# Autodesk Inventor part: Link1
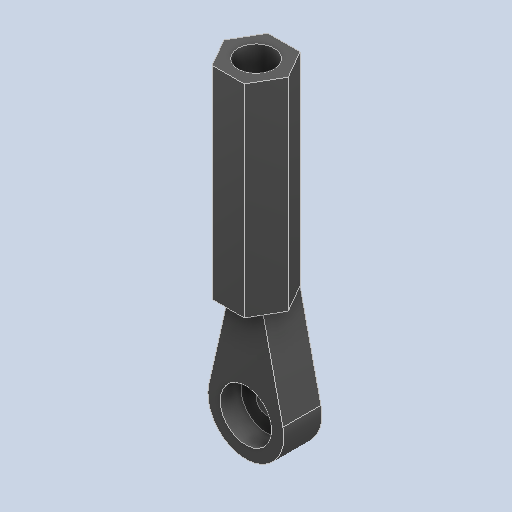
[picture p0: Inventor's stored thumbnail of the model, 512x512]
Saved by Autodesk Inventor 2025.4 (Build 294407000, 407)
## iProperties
Created: 2026-09
Part Number: Link1
Material: Generic
Document SubType Name: Modeling
Designer: AdminForWorker
Density: 1 g/cm^3
Appearance: Default
Title: Link1 v7 v1
Author: AdminForWorker
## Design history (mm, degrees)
feature "Body1"
body "Solid1"
